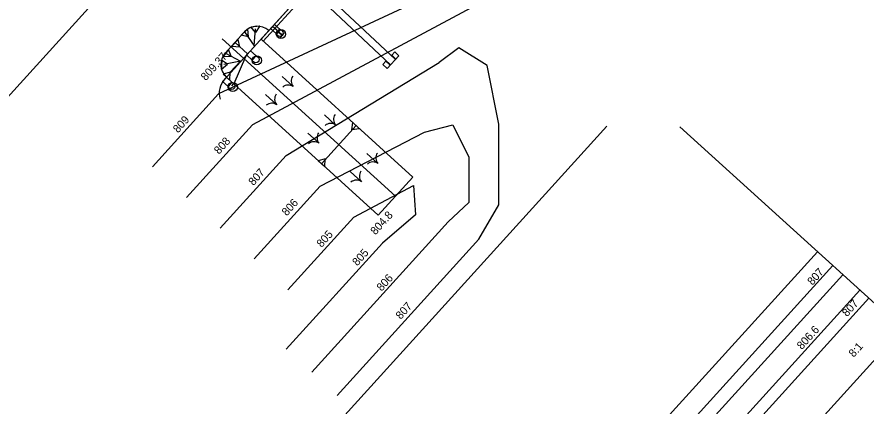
# Model space of a CAD drawing. Extents: x 1465887 to 1476191, y 569684 to 581027.
# Drawn here: x 1469566.9 to 1469715.4, y 573949.1 to 574017.1 of the extents above; entities that cross this region are included whole.
import ezdxf

# ---------------------------------------------------------------- set-up
doc = ezdxf.new("R2010")
doc.units = 0
for name, color, linetype in [('BR_P_Gen_Ground_Slope', 7, 'Continuous'), ('BR_P_Gen_Profile_Grade', 7, 'Continuous'), ('DR_P_Ditch', 7, 'Continuous'), ('DR_P_Erosion_Control', 7, 'Continuous'), ('DR_P_Headwall', 7, 'Continuous'), ('DR_P_Paved_Gutter', 7, 'Continuous'), ('DR_P_Storm_Sewer', 7, 'Continuous'), ('GK_Drainage_Nodes', 7, 'Continuous'), ('RD_P_Anchor_Assembly', 7, 'Continuous'), ('SC_Scratch1', 7, 'Continuous')]:
    doc.layers.add(name, color=color, linetype=linetype)

msp = doc.modelspace()

# ---------------------------------------------------------------- linework, layer by layer
at = {"layer": 'BR_P_Gen_Ground_Slope'}
for p, q in [((1469651.31, 574026.57), (1469602.16, 574003.67)), ((1469650.58, 574021.02), (1469608.08, 573998.29)), ((1469644.17, 574011.73), (1469640.77, 574009.14)), ((1469649.14, 574008.66), (1469644.17, 574011.73)), ((1469614, 573992.91), (1469640.77, 574009.14)), ((1469651.15, 573998.37), (1469649.14, 574008.66)), ((1469602.16, 574003.67), (1469590.62, 573990.96)), ((1469608.08, 573998.29), (1469596.54, 573985.59)), ((1469638.18, 573996.99), (1469643.12, 573998.27)), ((1469643.12, 573998.27), (1469645.94, 573992.64)), ((1469651.16, 573984.29), (1469651.15, 573998.37)), ((1469619.92, 573987.54), (1469638.18, 573996.99)), ((1469614, 573992.91), (1469602.46, 573980.21)), ((1469645.94, 573992.64), (1469645.95, 573984.7)), ((1469619.92, 573987.54), (1469608.38, 573974.83)), ((1469625.85, 573982.16), (1469636.24, 573987.67)), ((1469636.24, 573987.67), (1469636.6, 573982.55)), ((1469645.95, 573984.7), (1469642.33, 573981.32)), ((1469647.67, 573978.27), (1469651.16, 573984.29)), ((1469625.85, 573982.16), (1469614.31, 573969.45)), ((1469636.6, 573982.55), (1469630.86, 573977.6)), ((1469642.33, 573981.32), (1469618.46, 573955.02)), ((1469630.86, 573977.6), (1469614.02, 573959.06)), ((1469647.67, 573978.27), (1469622.9, 573950.99)), ((1469571.61, 573821.78), (1469709.56, 573973.68)), ((1469715.85, 573967.97), (1469695.33, 573945.37)), ((1469721.77, 573962.59), (1469701.25, 573940))]:
    msp.add_line(p, q, dxfattribs=at)
at = {"layer": 'BR_P_Gen_Profile_Grade'}
msp.add_line((1469397.14, 573817.97), (1469976.08, 574455.48), dxfattribs=at)
at = {"layer": 'DR_P_Ditch'}
msp.add_line((1469633.13, 573985.8), (1469602.82, 574013.33), dxfattribs=at)
at = {"layer": 'DR_P_Erosion_Control'}
for p, q in [((1469606.71, 574014.52), (1469603.34, 574010.82)), ((1469610.94, 574014.73), (1469609.6, 574013.25)), ((1469636.15, 573989.13), (1469609.6, 574013.25)), ((1469605.06, 574012.65), (1469607.23, 574010.7)), ((1469605.98, 574009.39), (1469604.2, 574007.45)), ((1469630.1, 573982.47), (1469603.55, 574006.58)), ((1469613.27, 574006.73), (1469615.23, 574004.95)), ((1469610.39, 574003.56), (1469612.35, 574001.78)), ((1469620.67, 574000.01), (1469622.64, 573998.23)), ((1469617.79, 573996.84), (1469619.75, 573995.05)), ((1469620.18, 573991.47), (1469626.24, 573998.13)), ((1469628.08, 573993.29), (1469630.04, 573991.5)), ((1469625.19, 573990.11), (1469627.16, 573988.33)), ((1469630.1, 573982.47), (1469636.15, 573989.13))]:
    msp.add_line(p, q, dxfattribs=at)
for points in [[(1469606.1, 574013.94), (1469607.25, 574015), (1469607.35, 574013.63)], [(1469607.82, 574015.37), (1469609.37, 574015.56), (1469608.64, 574014.38)], [(1469605.58, 574013.18), (1469604.51, 574012.04), (1469605.89, 574011.93)], [(1469603.89, 574011.45), (1469602.97, 574010.19), (1469604.35, 574010.25)], [(1469602.68, 574009.58), (1469602.67, 574008.02), (1469603.75, 574008.88)], [(1469602.96, 574007.1), (1469604.14, 574006.07), (1469604.2, 574007.45)], [(1469625.67, 573998.67), (1469626.81, 573997.6), (1469625.45, 573997.41)], [(1469625.67, 573998.67), (1469626.81, 573997.6), (1469625.45, 573997.41)], [(1469619.6, 573991.98), (1469620.77, 573990.95), (1469620.84, 573992.33)]]:
    msp.add_lwpolyline(points, close=True, dxfattribs=at)
for points in [[(1469606.7, 574014.53), (1469608.39, 574012.1), (1469608.62, 574015.03)], [(1469603.38, 574010.79), (1469605.98, 574009.39), (1469603.1, 574008.82)]]:
    msp.add_lwpolyline(points, dxfattribs=at)
for centre, radius, start, end in [((1469608.93, 574012.51), 3, 47.7565, 137.7565), ((1469605.57, 574008.81), 3, 137.7565, 227.7565), ((1469616.38, 574005.93), 1.51, 145.4729, 220.7345), ((1469614.36, 574003.72), 1.51, 54.7784, 130.04), ((1469613.49, 574002.76), 1.51, 145.4729, 220.7345), ((1469611.48, 574000.54), 1.51, 54.7784, 130.04), ((1469623.78, 573999.21), 1.51, 145.4729, 220.7345), ((1469621.77, 573997), 1.51, 54.7784, 130.04), ((1469620.9, 573996.04), 1.51, 145.4729, 220.7345), ((1469618.88, 573993.82), 1.51, 54.7784, 130.04), ((1469631.18, 573992.49), 1.51, 145.4729, 220.7345), ((1469629.17, 573990.27), 1.51, 54.7784, 130.04), ((1469628.3, 573989.31), 1.51, 145.4729, 220.7345), ((1469626.29, 573987.1), 1.51, 54.7784, 130.04)]:
    msp.add_arc(centre, radius, start, end, dxfattribs=at)
at = {"layer": 'DR_P_Headwall'}
msp.add_lwpolyline([(1469633.19, 574009.77), (1469632.46, 574010.46), (1469632.98, 574011.01), (1469633.71, 574010.32), (1469631.65, 574008.13), (1469630.92, 574008.82), (1469631.44, 574009.37), (1469632.17, 574008.68)], dxfattribs=at)
at = {"layer": 'DR_P_Paved_Gutter'}
for p, q in [((1469627.08, 574032.49), (1469609.6, 574013.25)), ((1469627.45, 574032.16), (1469609.97, 574012.91)), ((1469609.6, 574013.25), (1469609.97, 574012.91)), ((1469609.6, 574013.25), (1469609.97, 574012.91))]:
    msp.add_line(p, q, dxfattribs=at)
at = {"layer": 'DR_P_Storm_Sewer'}
for p, q in [((1469619.25, 574020.98), (1469632.25, 574008.77)), ((1469620.11, 574021.89), (1469633.11, 574009.68))]:
    msp.add_line(p, q, dxfattribs=at)
at = {"layer": 'GK_Drainage_Nodes'}
for p, q in [((1469631.95, 574009.91), (1469631.95, 574009.91)), ((1469632.68, 574009.23), (1469632.68, 574009.23)), ((1469632.68, 574009.23), (1469632.68, 574009.23)), ((1469632.68, 574009.23), (1469632.68, 574009.23)), ((1469632.68, 574009.23), (1469632.68, 574009.23)), ((1469632.68, 574009.23), (1469632.68, 574009.23))]:
    msp.add_line(p, q, dxfattribs=at)
at = {"layer": 'RD_P_Anchor_Assembly'}
for p, q in [((1469628.42, 574033.98), (1469611.62, 574015.47)), ((1469611.62, 574015.47), (1469603.21, 574006.21)), ((1469612.34, 574014.81), (1469611.62, 574015.47)), ((1469612.95, 574014.92), (1469612.29, 574014.19)), ((1469613.32, 574013.92), (1469612.59, 574014.59)), ((1469613.28, 574014.02), (1469612.68, 574014.56)), ((1469613.22, 574013.95), (1469612.62, 574014.49)), ((1469613.61, 574014.32), (1469612.95, 574013.59)), ((1469604.88, 574005.5), (1469606.92, 574010.19)), ((1469606.92, 574010.19), (1469607.13, 574010.42)), ((1469604.48, 574005.06), (1469604.86, 574005.47))]:
    msp.add_line(p, q, dxfattribs=at)
for points in [[(1469611.95, 574015.83), (1469611.28, 574015.1), (1469612.26, 574014.22), (1469612.92, 574014.95)], [(1469612.92, 574014.95), (1469612.26, 574014.22), (1469611.28, 574015.1), (1469611.95, 574015.83)], [(1469612.98, 574014.89), (1469612.32, 574014.16), (1469612.26, 574014.22), (1469612.92, 574014.95)], [(1469613.28, 574014.02), (1469613.22, 574013.95), (1469612.62, 574014.49), (1469612.68, 574014.56)], [(1469613.58, 574014.35), (1469612.92, 574013.62), (1469612.99, 574013.56), (1469613.65, 574014.29)], [(1469608.72, 574010.32), (1469608.05, 574009.59), (1469607.08, 574010.48), (1469607.74, 574011.21)], [(1469604.51, 574005.7), (1469603.85, 574004.97), (1469602.88, 574005.85), (1469603.54, 574006.58)]]:
    msp.add_lwpolyline(points, close=True, dxfattribs=at)
for points in [[(1469612.88, 574014.9), (1469612.92, 574014.95), (1469611.95, 574015.83), (1469611.28, 574015.1), (1469612.26, 574014.22), (1469612.3, 574014.27)], [(1469608.68, 574010.28), (1469608.72, 574010.32), (1469607.74, 574011.21), (1469607.08, 574010.48), (1469608.05, 574009.59), (1469608.1, 574009.64)], [(1469604.47, 574005.65), (1469604.51, 574005.7), (1469603.54, 574006.58), (1469602.88, 574005.85), (1469603.85, 574004.97), (1469603.89, 574005.01)]]:
    msp.add_lwpolyline(points, dxfattribs=at)
for centre, radius in [((1469613.07, 574014.14), 0.8), ((1469612.89, 574014.31), 0.591), ((1469608.87, 574009.53), 0.8), ((1469608.68, 574009.69), 0.591), ((1469604.67, 574004.87), 0.8), ((1469604.48, 574005.06), 0.591)]:
    msp.add_circle(centre, radius, dxfattribs=at)
msp.add_arc((1469605.92, 574003.8), 3.63, 138.1899, 196.2977, dxfattribs=at)
at = {"layer": 'SC_Scratch1'}
for p, q in [((1469537.85, 573852.43), (1469670.06, 573998.02)), ((1469682.83, 573997.95), (1469788.76, 573901.75)), ((1469568.95, 573824.2), (1469706.89, 573976.1)), ((1469573.39, 573820.16), (1469711.33, 573972.06)), ((1469576.35, 573817.47), (1469714.29, 573969.37))]:
    msp.add_line(p, q, dxfattribs=at)

# ---------------------------------------------------------------- texts
at = {"layer": 'BR_P_Gen_Ground_Slope'}
for s, p in [('809.37', (1469599.94, 574005.88)), ('809', (1469595.08, 573996.76)), ('808', (1469602.25, 573993.02)), ('807', (1469608.27, 573987.55)), ('806', (1469614.1, 573982.26)), ('804.8', (1469629.61, 573978.94)), ('805', (1469620.18, 573976.74)), ('805', (1469626.43, 573973.52)), ('807', (1469706, 573970.14)), ('806', (1469630.69, 573969.1)), ('807', (1469634.02, 573964.17)), ('807', (1469712.06, 573964.64)), ('806.6', (1469704.16, 573958.9)), ('8:1', (1469713.22, 573957.55))]:
    msp.add_text(s, height=1.4, rotation=47.7564, dxfattribs=at).set_placement(p)

doc.saveas('drawing.dxf')
